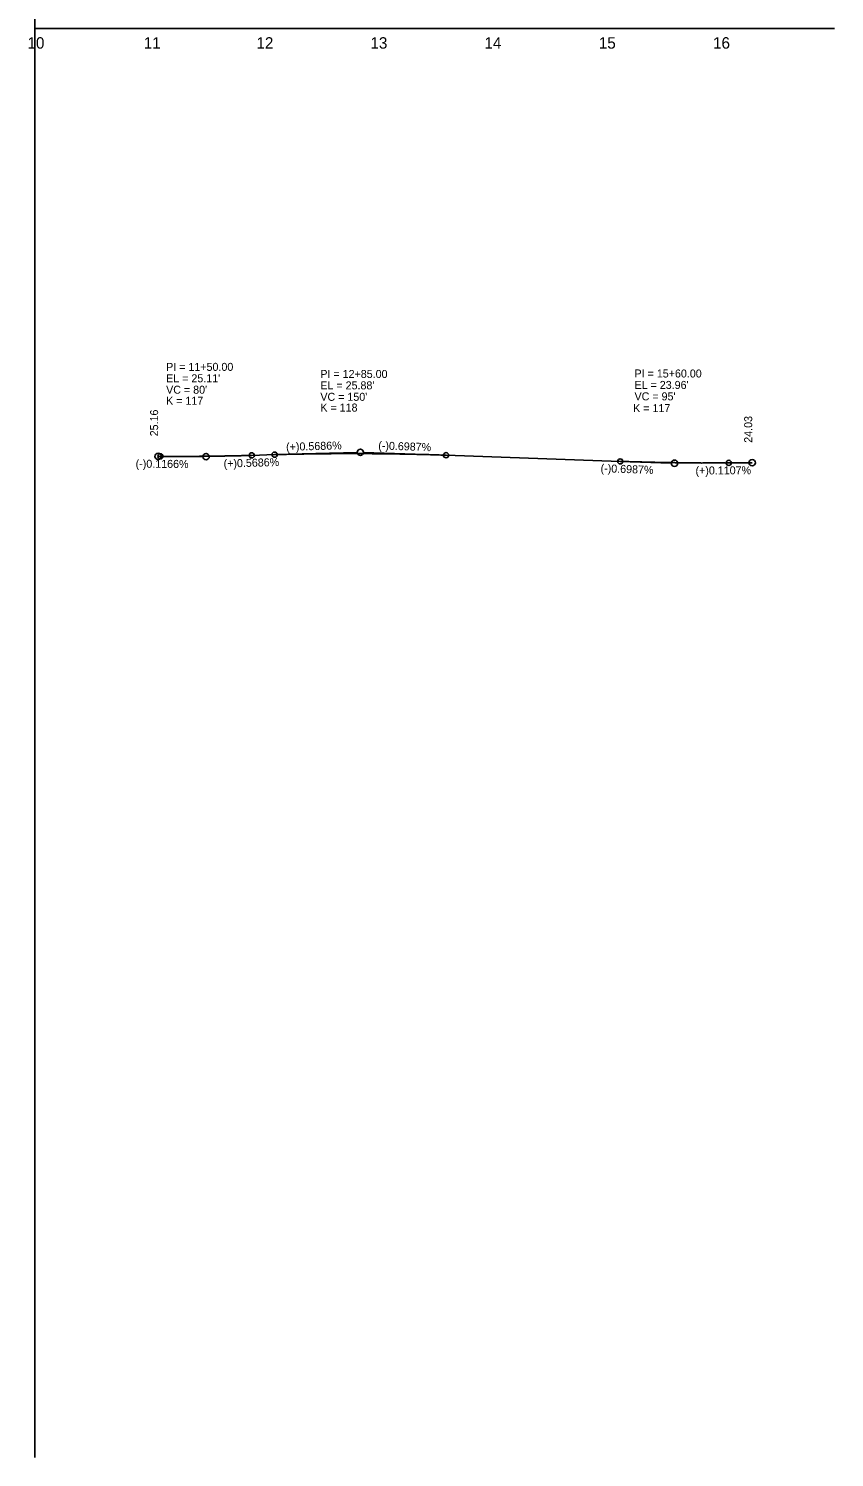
# Model space of a CAD drawing. Extents: x 2534543 to 2535313, y 713006 to 715506.
# Drawn here: x 2534569 to 2535275, y 713006 to 714256 of the extents above; entities that cross this region are included whole.
import ezdxf

# ---------------------------------------------------------------- set-up
doc = ezdxf.new("R2010")
doc.units = 0
for name, color, linetype in [('Exist Profile Cell', 7, 'Continuous'), ('Exist Vertical Profile Horizontal Axis Label Major', 7, 'Continuous'), ('Prop Vertical Profile Curve Label', 7, 'Continuous'), ('Prop Vertical Profile Grade', 7, 'Continuous'), ('Prop Vertical Profile Grade Label', 7, 'Continuous'), ('Prop VPI Label', 7, 'Continuous')]:
    doc.layers.add(name, color=color, linetype=linetype)

msp = doc.modelspace()

# ---------------------------------------------------------------- linework, layer by layer
at = {"layer": 'Exist Profile Cell'}
for q in [(2534574.9, 715505.8), (2535274.9, 714255.8), (2534574.9, 713005.8)]:
    msp.add_line((2534574.9, 714255.8), q, dxfattribs=at)
at = {"layer": 'Prop Vertical Profile Curve Label'}
for centre in [(2534684.9, 713881.6), (2534764.9, 713882.5), (2534784.9, 713883.1), (2534934.9, 713882.6), (2535087.4, 713877.2), (2535182.4, 713875.9)]:
    msp.add_circle(centre, 2.25, dxfattribs=at)
at = {"layer": 'Prop Vertical Profile Grade'}
for p, q in [((2534682.9, 713881.6), (2534684.9, 713881.6)), ((2534764.9, 713882.5), (2534784.9, 713883.1)), ((2534934.9, 713882.6), (2535087.4, 713877.2)), ((2535182.4, 713875.9), (2535202.9, 713876))]:
    msp.add_line(p, q, dxfattribs=at)
for points in [[(2534684.9, 713881.6), (2534686.5, 713881.6), (2534688.1, 713881.6), (2534689.7, 713881.6), (2534691.3, 713881.6), (2534692.9, 713881.6), (2534694.5, 713881.6), (2534696.1, 713881.6), (2534697.7, 713881.6), (2534699.3, 713881.6), (2534700.9, 713881.6), (2534702.5, 713881.6), (2534704.1, 713881.6), (2534705.7, 713881.6), (2534707.3, 713881.6), (2534708.9, 713881.6), (2534710.5, 713881.6), (2534712.1, 713881.6), (2534713.7, 713881.6), (2534715.3, 713881.6), (2534716.9, 713881.6), (2534718.5, 713881.6), (2534720.1, 713881.7), (2534721.7, 713881.7), (2534723.3, 713881.7), (2534724.9, 713881.7), (2534726.5, 713881.7), (2534728.1, 713881.7), (2534729.7, 713881.8), (2534731.3, 713881.8), (2534732.9, 713881.8), (2534734.5, 713881.8), (2534736.1, 713881.9), (2534737.7, 713881.9), (2534739.3, 713881.9), (2534740.9, 713881.9), (2534742.5, 713882), (2534744.1, 713882), (2534745.7, 713882), (2534747.3, 713882.1), (2534748.9, 713882.1), (2534750.5, 713882.1), (2534752.1, 713882.2), (2534753.7, 713882.2), (2534755.3, 713882.2), (2534756.9, 713882.3), (2534758.5, 713882.3), (2534760.1, 713882.4), (2534761.7, 713882.4), (2534763.3, 713882.4), (2534764.9, 713882.5)], [(2534784.9, 713883.1), (2534787.9, 713883.1), (2534790.9, 713883.2), (2534793.9, 713883.3), (2534796.9, 713883.4), (2534799.9, 713883.4), (2534802.9, 713883.5), (2534805.9, 713883.6), (2534808.9, 713883.6), (2534811.9, 713883.7), (2534814.9, 713883.7), (2534817.9, 713883.8), (2534820.9, 713883.8), (2534823.9, 713883.9), (2534826.9, 713883.9), (2534829.9, 713883.9), (2534832.9, 713883.9), (2534835.9, 713884), (2534838.9, 713884), (2534841.9, 713884), (2534844.9, 713884), (2534847.9, 713884), (2534850.9, 713884), (2534853.9, 713884), (2534856.9, 713884), (2534859.9, 713884), (2534862.9, 713884), (2534865.9, 713884), (2534868.9, 713884), (2534871.9, 713883.9), (2534874.9, 713883.9), (2534877.9, 713883.9), (2534880.9, 713883.8), (2534883.9, 713883.8), (2534886.9, 713883.8), (2534889.9, 713883.7), (2534892.9, 713883.7), (2534895.9, 713883.6), (2534898.9, 713883.6), (2534901.9, 713883.5), (2534904.9, 713883.4), (2534907.9, 713883.4), (2534910.9, 713883.3), (2534913.9, 713883.2), (2534916.9, 713883.1), (2534919.9, 713883.1), (2534922.9, 713883), (2534925.9, 713882.9), (2534928.9, 713882.8), (2534931.9, 713882.7), (2534934.9, 713882.6)], [(2535087.4, 713877.2), (2535089.3, 713877.2), (2535091.2, 713877.1), (2535093.1, 713877.1), (2535095, 713877), (2535096.9, 713876.9), (2535098.8, 713876.9), (2535100.7, 713876.8), (2535102.6, 713876.8), (2535104.5, 713876.7), (2535106.4, 713876.7), (2535108.3, 713876.6), (2535110.2, 713876.6), (2535112.1, 713876.5), (2535114, 713876.5), (2535115.9, 713876.4), (2535117.8, 713876.4), (2535119.7, 713876.3), (2535121.6, 713876.3), (2535123.5, 713876.3), (2535125.4, 713876.2), (2535127.3, 713876.2), (2535129.2, 713876.2), (2535131.1, 713876.1), (2535133, 713876.1), (2535134.9, 713876.1), (2535136.8, 713876), (2535138.7, 713876), (2535140.6, 713876), (2535142.5, 713876), (2535144.4, 713875.9), (2535146.3, 713875.9), (2535148.2, 713875.9), (2535150.1, 713875.9), (2535152, 713875.9), (2535153.9, 713875.9), (2535155.8, 713875.9), (2535157.7, 713875.8), (2535159.6, 713875.8), (2535161.5, 713875.8), (2535163.4, 713875.8), (2535165.3, 713875.8), (2535167.2, 713875.8), (2535169.1, 713875.8), (2535171, 713875.8), (2535172.9, 713875.8), (2535174.8, 713875.8), (2535176.7, 713875.8), (2535178.6, 713875.8), (2535180.5, 713875.8), (2535182.4, 713875.9)]]:
    msp.add_spline(points, degree=3, dxfattribs=at)
at = {"layer": 'Prop VPI Label'}
for p, q in [((2534684.9, 713881.6), (2534722.1, 713881.4)), ((2534764.9, 713882.5), (2534727.6, 713881.4)), ((2534784.9, 713883.1), (2534857.1, 713885.1)), ((2534934.9, 713882.6), (2534862.6, 713885.1)), ((2535087.4, 713877.2), (2535132.1, 713875.7)), ((2535182.4, 713875.9), (2535137.6, 713875.6))]:
    msp.add_line(p, q, dxfattribs=at)
for centre in [(2534682.9, 713881.6), (2534724.9, 713881.4), (2534859.9, 713885.2), (2535134.9, 713875.6), (2535202.9, 713876)]:
    msp.add_circle(centre, 2.75, dxfattribs=at)

# ---------------------------------------------------------------- texts
at = {"layer": 'Exist Vertical Profile Horizontal Axis Label Major'}
for s, p in [('10', (2534568.5, 714238.3)), ('11', (2534670.3, 714238.3)), ('12', (2534768.9, 714238.3)), ('13', (2534868.7, 714238.3)), ('14', (2534968.5, 714238.3)), ('15', (2535068.6, 714238.3)), ('16', (2535168.6, 714238.3))]:
    msp.add_text(s, height=10, dxfattribs=at).set_placement(p)
at = {"layer": 'Prop Vertical Profile Curve Label'}
for s, p in [("VC = 80'", (2534689.9, 713936.4)), ('K = 117', (2534689.9, 713926.8)), ("VC = 150'", (2534824.9, 713930.2)), ("VC = 95'", (2535099.9, 713930.6)), ('K = 118', (2534824.9, 713920.8)), ('K = 117', (2535098.7, 713920.3))]:
    msp.add_text(s, height=7, dxfattribs=at).set_placement(p)
at = {"layer": 'Prop Vertical Profile Grade Label'}
for s, rotation, p in [('(+)0.5686%', 1.6285, (2534795, 713886.4)), ('(-)0.6987%', 357.9992, (2534875.5, 713887.7)), ('(-)0.1166%', 359.6659, (2534663.2, 713871.7)), ('(+)0.5686%', 1.6285, (2534740.3, 713871.8)), ('(-)0.6987%', 357.9992, (2535070.1, 713867.8)), ('(+)0.1107%', 0.317, (2535153.3, 713865.7))]:
    msp.add_text(s, height=7, rotation=rotation, dxfattribs=at).set_placement(p)
at = {"layer": 'Prop VPI Label'}
for s, p in [('PI = 11+50.00', (2534689.9, 713956.4)), ('PI = 12+85.00', (2534824.9, 713950.2)), ('PI = 15+60.00', (2535099.9, 713950.6)), ("EL = 25.11'", (2534689.9, 713946.4)), ("EL = 25.88'", (2534824.9, 713940.2)), ("EL = 23.96'", (2535099.9, 713940.6))]:
    msp.add_text(s, height=7, dxfattribs=at).set_placement(p)
for s, p in [('25.16', (2534682.9, 713899.1)), ('24.03', (2535202.9, 713893.5))]:
    msp.add_text(s, height=7, rotation=90, dxfattribs=at).set_placement(p)

doc.saveas('drawing.dxf')
